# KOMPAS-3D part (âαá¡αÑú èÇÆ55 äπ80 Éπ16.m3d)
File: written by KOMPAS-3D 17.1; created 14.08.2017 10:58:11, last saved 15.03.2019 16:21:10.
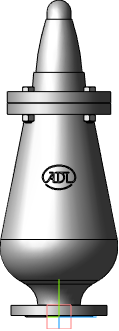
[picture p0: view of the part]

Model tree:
1. Операция без истории:2  (labels: Сталь 20  ГОСТ 1050-2013)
